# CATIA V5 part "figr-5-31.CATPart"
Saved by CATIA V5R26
Part number: Part1
Bounding box of the stored display mesh (mm): x -32.491 to 32.491, y -32.393 to 32.5, z 0 to 85.656
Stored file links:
  D:\_Deepak\CATIA\CATIA V5-6R2016_Deepak\Resources\Part files\Partfiles\c05_catia_v5_6r2016_prt\figr-5-31.CATPart
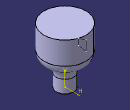
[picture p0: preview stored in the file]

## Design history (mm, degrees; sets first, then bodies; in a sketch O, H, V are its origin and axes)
Body1 (main body)
  Sketch1 on yz-plane, origin (0, 0, 0), H (0, 1, 0), V (0, 0, 1)
    axis line L1 (0, 0) -> (0, 100.0993)
    line L2 (0, 0) -> (13.3295, 0)
    line L3 (13.3295, 0) -> (13.3295, 19.6564)
    arc A1 centre (31.7623, 19.6564) radius 18.4328 from (13.3295, 19.6564) to (23.518, 36.1427) cw
    arc A2 centre (16.25, 50.6768) radius 16.25 from (23.518, 36.1427) to (32.5, 50.6768) ccw
    line L4 (32.5, 50.6768) -> (32.5, 85.6563)
    line L5 (32.5, 85.6563) -> (0, 85.6563)
    point P9 (0, 85.6563)
    line L6 (0, 85.6563) -> (0, 0)
    radius about axis L4 L1 = 32.5
    vertical: L1 V, L3 V, L4 V
    horizontal: L2 H, L5 H
    tangency: A1 L3, A2 L1, A2 A1, L4 A2, L6 A2
    coincidence: P9 L1
  Shaft1: profile Sketch1, axis Sketch1.L1, angle 360
  Sketch2 on yz-plane, origin (0, 0, 0), H (0, 1, 0), V (0, 0, 1)
    axis line L1 (0, 0) -> (0, 91.1904)
    point P1 (0, 0)
    point P2 (0, 91.1904)
    line L2 (32.5, 78.7512) -> (21.4593, 75.7196)
    line L3 (21.4593, 75.7196) -> (21.4593, 66.4534)
    line L4 (21.4593, 66.4534) -> (32.5, 63.9927)
    line L5 (32.5, 63.9927) -> (32.5, 78.7512)
    coincidence: P1 H, P2 V
    vertical: L1 V, L3 V, L5 V
  Groove1: profile Sketch2, axis Sketch2.L1, angle 360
